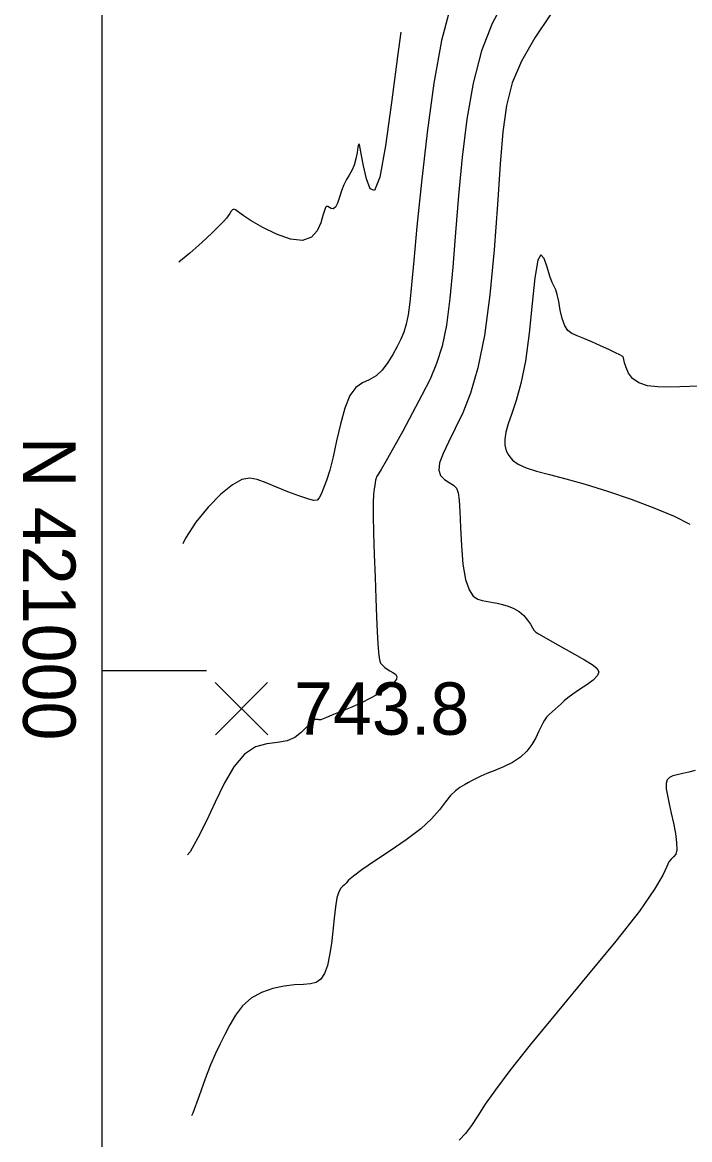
# Model space of a CAD drawing. Extents: x 2566142 to 2571431, y 418755 to 421584.
# Drawn here: x 2566141.7 to 2566332.7, y 420865.6 to 421185.7 of the extents above; entities that cross this region are included whole.
import ezdxf

# ---------------------------------------------------------------- set-up
doc = ezdxf.new("R2010")
doc.units = 0
for name, color, linetype in [('Contour_ADS_Major', 7, 'Continuous'), ('Contour_ADS_Minor', 7, 'Continuous'), ('Contour_ADS_Spot_Elevation', 7, 'Continuous'), ('Contour_ADS_State_Plane_Border', 7, 'Continuous')]:
    doc.layers.add(name, color=color, linetype=linetype)

# ---------------------------------------------------------------- blocks, each defined once
blk = doc.blocks.new('S750')
at = {"layer": 'Contour_ADS_Spot_Elevation'}
for p, q in [((-0.5, 0.498), (0.5, -0.498)), ((-0.498, -0.5), (0.498, 0.5))]:
    blk.add_line(p, q, dxfattribs=at)

msp = doc.modelspace()

# ---------------------------------------------------------------- linework, layer by layer
at = {"layer": 'Contour_ADS_Major'}
msp.add_lwpolyline([(2566250.08, 421182.9), (2566249.1, 421175.88), (2566247.39, 421162.67), (2566245.65, 421150.3), (2566244, 421141.31), (2566242.52, 421137.53), (2566241.25, 421137.95), (2566240.19, 421140.86), (2566239.38, 421144.53), (2566238.81, 421147.55), (2566238.43, 421149.61), (2566238.17, 421150.68), (2566237.97, 421150.77), (2566237.77, 421149.9), (2566237.51, 421148.37), (2566237.15, 421146.53), (2566236.67, 421144.73), (2566236.03, 421143.22), (2566235.29, 421141.92), (2566234.51, 421140.62), (2566233.75, 421139.14), (2566233.07, 421137.38), (2566232.46, 421135.54), (2566231.88, 421133.9), (2566231.3, 421132.75), (2566230.71, 421132.29), (2566230.13, 421132.33), (2566229.59, 421132.63), (2566229.14, 421132.92), (2566228.79, 421132.96), (2566228.49, 421132.62), (2566228.17, 421131.78), (2566227.75, 421130.31), (2566227.12, 421128.23), (2566226.09, 421125.97), (2566224.43, 421124.1), (2566221.91, 421123.18), (2566218.44, 421123.58), (2566214.46, 421124.99), (2566210.51, 421126.9), (2566207.19, 421128.81), (2566204.9, 421130.31), (2566203.5, 421131.34), (2566202.71, 421131.93), (2566202.24, 421132.13), (2566201.84, 421131.97), (2566201.46, 421131.54), (2566201.07, 421130.95), (2566200.65, 421130.28), (2566200.15, 421129.57), (2566199.37, 421128.67), (2566198.07, 421127.34), (2566196.01, 421125.36), (2566193.08, 421122.64), (2566189.63, 421119.57), (2566186.48, 421116.94)], dxfattribs=at)
at = {"layer": 'Contour_ADS_Minor'}
for points in [[(2566279.63, 421191.74), (2566276.22, 421185.33), (2566273.13, 421177.5), (2566270.72, 421168.25), (2566268.92, 421157.96), (2566267.59, 421147.09), (2566266.57, 421136.11), (2566265.72, 421125.46), (2566264.92, 421115.49), (2566264.08, 421106.55), (2566263.08, 421098.95), (2566261.84, 421092.88), (2566260.3, 421087.9), (2566258.4, 421083.42), (2566256.1, 421078.85), (2566253.42, 421073.77), (2566250.6, 421068.56), (2566247.97, 421063.79), (2566245.83, 421060), (2566244.42, 421057.61), (2566243.63, 421056.34), (2566243.25, 421055.76), (2566243.08, 421055.46), (2566242.95, 421055.06), (2566242.83, 421054.51), (2566242.7, 421053.82), (2566242.56, 421053.01), (2566242.4, 421052.01), (2566242.26, 421050.51), (2566242.16, 421048.13), (2566242.15, 421044.47), (2566242.26, 421039.34), (2566242.45, 421033.21), (2566242.68, 421026.75), (2566242.91, 421020.62), (2566243.12, 421015.36), (2566243.3, 421011.07), (2566243.46, 421007.72), (2566243.63, 421005.27), (2566243.8, 421003.65), (2566244.01, 421002.68), (2566244.26, 421002.11), (2566244.59, 421001.71), (2566245, 421001.29), (2566245.51, 421000.82), (2566246.13, 421000.34), (2566246.89, 420999.87), (2566247.73, 420999.41), (2566248.49, 420998.91), (2566248.92, 420998.29), (2566248.79, 420997.45), (2566247.92, 420996.36), (2566246.37, 420995.05), (2566244.22, 420993.61), (2566241.58, 420992.13), (2566238.58, 420990.66), (2566235.5, 420989.3), (2566232.64, 420988.11), (2566230.32, 420987.17), (2566228.75, 420986.54), (2566227.83, 420986.16), (2566227.35, 420985.96), (2566227.12, 420985.87), (2566226.94, 420985.83), (2566226.78, 420985.83), (2566226.59, 420985.85), (2566226.34, 420985.9), (2566225.99, 420985.96), (2566225.51, 420985.89), (2566224.87, 420985.56), (2566224.02, 420984.83)], [(2566264.06, 421189.45), (2566261.7, 421180.44), (2566259.51, 421168.21), (2566257.56, 421154.1), (2566255.92, 421139.84), (2566254.64, 421127.18), (2566253.73, 421117.47), (2566253.1, 421110.45), (2566252.62, 421105.47), (2566252.16, 421101.91), (2566251.59, 421099.17), (2566250.9, 421096.92), (2566250.04, 421094.89), (2566249, 421092.82), (2566247.76, 421090.53), (2566246.34, 421088.18), (2566244.73, 421086.04), (2566242.94, 421084.37), (2566241.02, 421083.28), (2566239.05, 421082.36), (2566237.14, 421081.03), (2566235.43, 421078.75), (2566233.98, 421075.13), (2566232.75, 421070.59), (2566231.67, 421065.74), (2566230.67, 421061.19), (2566229.68, 421057.41), (2566228.75, 421054.44), (2566227.91, 421052.18), (2566227.23, 421050.53), (2566226.7, 421049.41), (2566226.08, 421048.8), (2566225.08, 421048.7), (2566223.4, 421049.12), (2566220.86, 421050), (2566217.75, 421051.2), (2566214.48, 421052.52), (2566211.46, 421053.75), (2566208.97, 421054.69), (2566206.78, 421055.09), (2566204.53, 421054.68), (2566201.87, 421053.2), (2566198.57, 421050.48), (2566194.94, 421046.78), (2566191.41, 421042.45), (2566188.43, 421037.86), (2566187.69, 421036.3)], [(2566292.85, 421187.92), (2566288.37, 421181.22), (2566284.56, 421174.57), (2566281.93, 421168.3), (2566280.28, 421161.83), (2566279.26, 421154.34), (2566278.51, 421145.04), (2566277.71, 421133.45), (2566276.75, 421120.54), (2566275.54, 421107.62), (2566274.01, 421095.99), (2566272.13, 421086.66), (2566270, 421079.44), (2566267.78, 421073.82), (2566265.63, 421069.28), (2566263.69, 421065.41), (2566262.13, 421062.12), (2566261.14, 421059.43), (2566260.88, 421057.33), (2566261.43, 421055.8), (2566262.55, 421054.7), (2566263.89, 421053.85), (2566265.11, 421053.1), (2566265.96, 421052.23), (2566266.47, 421050.92), (2566266.75, 421048.82), (2566266.93, 421045.57), (2566267.11, 421040.99), (2566267.39, 421035.69), (2566267.84, 421030.44), (2566268.55, 421026.03), (2566269.57, 421023.04), (2566270.79, 421021.3), (2566272.09, 421020.42), (2566273.32, 421020.02), (2566274.39, 421019.8), (2566275.38, 421019.63), (2566276.43, 421019.46), (2566277.64, 421019.24), (2566279.11, 421018.92), (2566280.73, 421018.45), (2566282.38, 421017.78), (2566283.92, 421016.87), (2566285.23, 421015.71), (2566286.3, 421014.44), (2566287.12, 421013.23), (2566287.7, 421012.24), (2566288.1, 421011.57), (2566288.57, 421011.07), (2566289.44, 421010.49), (2566291.01, 421009.58), (2566293.48, 421008.2), (2566296.54, 421006.49), (2566299.73, 421004.69), (2566302.6, 421003.04), (2566304.79, 421001.71), (2566306.18, 421000.61), (2566306.71, 420999.59), (2566306.34, 420998.51), (2566305.08, 420997.25), (2566303.24, 420995.88), (2566301.19, 420994.51), (2566299.29, 420993.24), (2566297.84, 420992.17), (2566296.76, 420991.24), (2566295.9, 420990.43), (2566295.1, 420989.66), (2566294.25, 420988.9), (2566293.37, 420988.13), (2566292.53, 420987.36), (2566291.78, 420986.58), (2566291.18, 420985.77), (2566290.65, 420984.86), (2566290.11, 420983.76), (2566289.47, 420982.39), (2566288.66, 420980.7), (2566287.58, 420978.82), (2566286.15, 420976.9), (2566284.3, 420975.13), (2566281.99, 420973.63), (2566279.44, 420972.39), (2566276.92, 420971.35), (2566274.69, 420970.49), (2566272.95, 420969.74)], [(2566334.97, 421081.44), (2566332.65, 421081.35), (2566329.91, 421081.25), (2566326.82, 421081.17), (2566323.63, 421081.23), (2566320.63, 421081.57), (2566318.13, 421082.35), (2566316.34, 421083.63), (2566315.19, 421085.21), (2566314.5, 421086.82), (2566314.11, 421088.16), (2566313.89, 421089.05), (2566313.77, 421089.53), (2566313.72, 421089.74), (2566313.69, 421089.82), (2566313.62, 421089.88), (2566313.36, 421090.03), (2566312.71, 421090.37), (2566311.48, 421090.97), (2566309.57, 421091.9), (2566307.21, 421093.02), (2566304.71, 421094.16), (2566302.39, 421095.13), (2566300.48, 421095.84), (2566298.99, 421096.49), (2566297.84, 421097.37), (2566296.95, 421098.75), (2566296.26, 421100.8), (2566295.7, 421103.23), (2566295.24, 421105.65), (2566294.82, 421107.66), (2566294.4, 421109), (2566293.93, 421110.01), (2566293.39, 421111.16), (2566292.72, 421112.94), (2566291.92, 421115.54), (2566291.03, 421118.01), (2566290.11, 421119.08), (2566289.22, 421117.52), (2566288.41, 421112.52), (2566287.61, 421105.08), (2566286.74, 421096.64), (2566285.69, 421088.63), (2566284.44, 421082.21)], [(2566284.44, 421082.21), (2566283.09, 421077.31), (2566281.81, 421073.58), (2566280.77, 421070.67), (2566280.1, 421068.27), (2566279.8, 421066.24), (2566279.85, 421064.49), (2566280.22, 421062.95), (2566280.92, 421061.54), (2566282.02, 421060.24), (2566283.64, 421059.07), (2566285.89, 421058.02), (2566288.86, 421057.08), (2566292.63, 421056.1), (2566297.25, 421054.93), (2566302.78, 421053.39), (2566309.17, 421051.38), (2566315.95, 421049.05), (2566322.51, 421046.57), (2566328.27, 421044.16), (2566332.81, 421041.93)], [(2566224.02, 420984.83), (2566222.93, 420983.63), (2566221.52, 420982.19), (2566219.73, 420980.82), (2566217.48, 420979.83), (2566214.75, 420979.37), (2566211.67, 420978.99), (2566208.45, 420978.08), (2566205.27, 420976.02), (2566202.29, 420972.42), (2566199.5, 420967.63), (2566196.88, 420962.26), (2566194.38, 420956.87), (2566191.98, 420952), (2566189.7, 420948.01), (2566189.02, 420947.12)], [(2566272.95, 420969.74), (2566271.6, 420969.07), (2566270.47, 420968.46), (2566269.39, 420967.86), (2566268.23, 420967.23), (2566266.97, 420966.47), (2566265.65, 420965.48), (2566264.29, 420964.12), (2566262.87, 420962.32), (2566261.16, 420960.1), (2566258.87, 420957.51), (2566255.73, 420954.6), (2566251.61, 420951.45), (2566247, 420948.28), (2566242.53, 420945.34), (2566238.86, 420942.88), (2566236.46, 420941.09), (2566235.11, 420939.87), (2566234.41, 420939.08), (2566233.96, 420938.57), (2566233.45, 420938.16), (2566232.87, 420937.6), (2566232.28, 420936.6), (2566231.74, 420934.88), (2566231.3, 420932.26), (2566230.93, 420928.97), (2566230.57, 420925.34), (2566230.16, 420921.72), (2566229.66, 420918.39), (2566229.03, 420915.5), (2566228.21, 420913.18), (2566227.17, 420911.52), (2566225.85, 420910.58), (2566224.2, 420910.17), (2566222.15, 420910.03), (2566219.63, 420909.89), (2566216.64, 420909.54), (2566213.39, 420908.85), (2566210.15, 420907.73), (2566207.21, 420906.09), (2566204.76, 420903.88), (2566202.76, 420901.27), (2566201.1, 420898.46), (2566199.65, 420895.66), (2566198.3, 420892.99), (2566196.98, 420890.21), (2566195.59, 420886.99), (2566194.05, 420883), (2566192.31, 420878.14), (2566190.47, 420873.15), (2566190.14, 420872.4)], [(2566327.89, 420969.75), (2566326.93, 420969.31), (2566326.31, 420968.64), (2566326.01, 420967.6), (2566326.04, 420966.09), (2566326.33, 420964.14), (2566326.81, 420961.8), (2566327.42, 420959.12), (2566328.06, 420956.2), (2566328.63, 420953.28), (2566329, 420950.65), (2566329.06, 420948.61), (2566328.74, 420947.32), (2566328.14, 420946.55), (2566327.42, 420945.94), (2566326.76, 420945.14), (2566326.17, 420943.78), (2566325.05, 420941.34), (2566322.68, 420937.28), (2566318.33, 420931.06), (2566311.58, 420922.44), (2566303.31, 420912.36), (2566294.75, 420902.05), (2566287.09, 420892.75), (2566281.28, 420885.41), (2566277.14, 420879.87), (2566274.21, 420875.68), (2566272.05, 420872.4), (2566270.23, 420869.64), (2566268.53, 420867.31), (2566266.75, 420865.39)], [(2566334.32, 420971.32), (2566332.49, 420970.85), (2566330.73, 420970.44), (2566329.16, 420970.09), (2566327.89, 420969.75)]]:
    msp.add_lwpolyline(points, dxfattribs=at)
at = {"layer": 'Contour_ADS_State_Plane_Border'}
msp.add_line((2566164.43, 421000), (2566194.43, 421000), dxfattribs=at)
msp.add_lwpolyline([(2566164.43, 418777.5), (2571407.81, 418777.5), (2571407.81, 421561.67), (2566164.43, 421561.67), (2566164.43, 418777.5)], close=True, dxfattribs=at)

# ---------------------------------------------------------------- block references
at = {"layer": 'Contour_ADS_Spot_Elevation', "xscale": 15, "yscale": 15}
msp.add_blockref('S750', (2566204.45, 420989.06), dxfattribs=at)

# ---------------------------------------------------------------- texts
at = {"layer": 'Contour_ADS_Spot_Elevation'}
msp.add_text('743.8', height=15, dxfattribs=at).set_placement((2566219.45, 420981.56))
at = {"layer": 'Contour_ADS_State_Plane_Border'}
msp.add_text(' N 421000', height=15, rotation=270, dxfattribs=at).set_placement((2566141.93, 421072.5))

doc.saveas('drawing.dxf')
